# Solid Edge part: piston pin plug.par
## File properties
Author: Robert a Rhodes jr
Template: Normal.par
Last saved by: CADCIM
Revision: 12
Application: Solid Edge
Accuracy: 0.99
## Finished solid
Body 1: solid body, 6 faces, 5 edges, 0 vertices.
  Faces by surface: plane 3, cylinder 2, torus 1
  Edges by curve: circle 5
Bounding box of the edges (mm; curved faces can reach further): 22.000 x 22.000 x 15.000, from (-11, -11, -12) to (11, 11, 3).
Cylindrical faces by radius (mm): R5.5 x1, R11 x1
Toroidal faces (ring radius, tube radius in mm): R9 r2 x1
Planar faces by outward normal: +z 1, -z 2
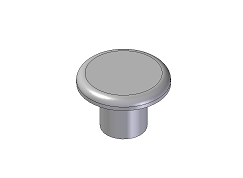
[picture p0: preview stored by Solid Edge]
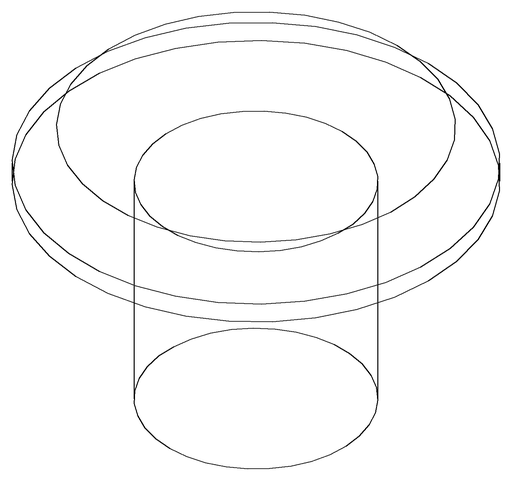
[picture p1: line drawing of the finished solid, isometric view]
